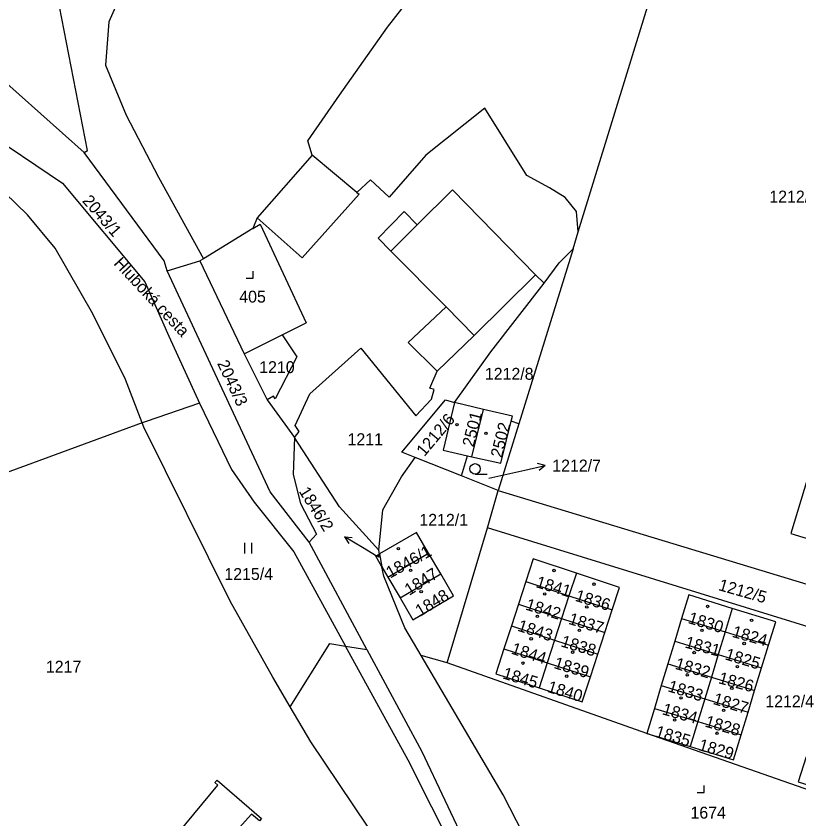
# Model space of a CAD drawing. Extents: x -679220 to -673243, y -1075091 to -1066557.
# Drawn here: x -676840.9 to -676729.1, y -1070923.7 to -1070809.1 of the extents above; entities that cross this region are included whole.
import ezdxf

# ---------------------------------------------------------------- set-up
doc = ezdxf.new("R2010")
doc.units = 0
for name, color, linetype in [('Hranice parcel', 7, 'Continuous'), ('Parcelní čísla', 7, 'Continuous'), ('Pop  PČ popisy', 7, 'Continuous'), ('Vnitřní kresba', 7, 'Continuous'), ('Značky budov', 7, 'Continuous'), ('Značky kultur', 7, 'Continuous')]:
    doc.layers.add(name, color=color, linetype=linetype)

msp = doc.modelspace()

# ---------------------------------------------------------------- linework, layer by layer
at = {"layer": 'Hranice parcel'}
for p, q in [((-676850.18, -1070811.62), (-676831.16, -1070828.55)), ((-676761.35, -1070842.3), (-676760.61, -1070839.9)), ((-676761.35, -1070842.3), (-676769.07, -1070867.29)), ((-676819.29, -1070845.47), (-676814.64, -1070844.06)), ((-676814.12, -1070843.75), (-676814.64, -1070844.06)), ((-676814.64, -1070844.06), (-676808.28, -1070857.3)), ((-676808.28, -1070857.3), (-676805.03, -1070863.88)), ((-676805.03, -1070863.88), (-676801.1, -1070869.26)), ((-676774.15, -1070865.26), (-676778.29, -1070864.28)), ((-676775.78, -1070872.01), (-676774.15, -1070865.26)), ((-676769.07, -1070867.29), (-676772.02, -1070876.85)), ((-676769.07, -1070867.29), (-676770.18, -1070866.92)), ((-676777.29, -1070874.76), (-676783.89, -1070872.14)), ((-676777.29, -1070874.76), (-676776.4, -1070871.87)), ((-676776.4, -1070871.87), (-676775.78, -1070872.01)), ((-676772.02, -1070876.85), (-676777.29, -1070874.76)), ((-676773.55, -1070882.16), (-676772.02, -1070876.85)), ((-676772.02, -1070876.85), (-676699.58, -1070898.82)), ((-676779.3, -1070901.45), (-676773.55, -1070882.16)), ((-676696.97, -1070905.8), (-676773.55, -1070882.16)), ((-676790.8, -1070899.53), (-676799.03, -1070884.19)), ((-676788.98, -1070885.89), (-676789.09, -1070885.34)), ((-676788.98, -1070885.89), (-676788.63, -1070887.71)), ((-676787.77, -1070889.19), (-676781.97, -1070885.79)), ((-676780.23, -1070888.75), (-676781.97, -1070885.79)), ((-676788.63, -1070887.71), (-676787.77, -1070889.19)), ((-676787.77, -1070889.19), (-676786.03, -1070892.17)), ((-676786.03, -1070892.17), (-676780.23, -1070888.75)), ((-676760.88, -1070888.63), (-676761.93, -1070891.86)), ((-676768.09, -1070889.83), (-676769.15, -1070893.08)), ((-676768.09, -1070889.83), (-676761.93, -1070891.86)), ((-676761.93, -1070891.86), (-676762.99, -1070895.1)), ((-676761.93, -1070891.86), (-676755.78, -1070893.89)), ((-676769.15, -1070893.08), (-676770.16, -1070896.18)), ((-676769.15, -1070893.08), (-676762.99, -1070895.1)), ((-676756.83, -1070897.12), (-676755.78, -1070893.89)), ((-676738.62, -1070893.67), (-676739.64, -1070897.02)), ((-676762.99, -1070895.1), (-676763.99, -1070898.2)), ((-676762.99, -1070895.1), (-676756.83, -1070897.12)), ((-676745.85, -1070895.11), (-676746.83, -1070898.36)), ((-676745.85, -1070895.11), (-676739.64, -1070897.02)), ((-676770.16, -1070896.18), (-676771.21, -1070899.42)), ((-676770.16, -1070896.18), (-676763.99, -1070898.2)), ((-676757.83, -1070900.21), (-676756.83, -1070897.12)), ((-676739.64, -1070897.02), (-676740.63, -1070900.26)), ((-676739.64, -1070897.02), (-676733.45, -1070898.92)), ((-676763.99, -1070898.2), (-676765.05, -1070901.43)), ((-676763.99, -1070898.2), (-676757.83, -1070900.21)), ((-676746.83, -1070898.36), (-676747.81, -1070901.6)), ((-676746.83, -1070898.36), (-676740.63, -1070900.26)), ((-676793.82, -1070899.05), (-676790.8, -1070899.53)), ((-676771.21, -1070899.42), (-676765.05, -1070901.43)), ((-676734.44, -1070902.16), (-676733.45, -1070898.92)), ((-676779.3, -1070901.45), (-676783.03, -1070900.39)), ((-676758.87, -1070903.44), (-676757.83, -1070900.21)), ((-676740.63, -1070900.26), (-676741.61, -1070903.5)), ((-676740.63, -1070900.26), (-676734.44, -1070902.16)), ((-676765.05, -1070901.43), (-676766.21, -1070905)), ((-676765.05, -1070901.43), (-676758.87, -1070903.44)), ((-676747.81, -1070901.6), (-676748.75, -1070904.69)), ((-676747.81, -1070901.6), (-676741.61, -1070903.5)), ((-676735.43, -1070905.39), (-676734.44, -1070902.16)), ((-676741.61, -1070903.5), (-676742.56, -1070906.59)), ((-676741.61, -1070903.5), (-676735.43, -1070905.39)), ((-676748.75, -1070904.69), (-676749.74, -1070907.94)), ((-676748.75, -1070904.69), (-676742.56, -1070906.59)), ((-676736.37, -1070908.49), (-676735.43, -1070905.39)), ((-676742.56, -1070906.59), (-676743.55, -1070909.83)), ((-676742.56, -1070906.59), (-676736.37, -1070908.49)), ((-676749.74, -1070907.94), (-676743.55, -1070909.83)), ((-676737.36, -1070911.72), (-676736.37, -1070908.49)), ((-676743.55, -1070909.83), (-676744.63, -1070913.39)), ((-676743.55, -1070909.83), (-676737.36, -1070911.72))]:
    msp.add_line(p, q, dxfattribs=at)
for points in [[(-676734.09, -1070729.39), (-676764.56, -1070754.12), (-676779.02, -1070765.48), (-676780.93, -1070766.95), (-676802.84, -1070783.93), (-676807.58, -1070787.57), (-676808.32, -1070787.51), (-676809.11, -1070788.09), (-676821.6, -1070800.12), (-676825.36, -1070804.84), (-676827.62, -1070809.91), (-676828.1, -1070816.09), (-676825.15, -1070823.23), (-676820.55, -1070832.07), (-676814.12, -1070843.75)], [(-676798.59, -1070828.95), (-676799.22, -1070826.91), (-676794.71, -1070820.4), (-676787.84, -1070810.66), (-676782.89, -1070804.27), (-676771.75, -1070792.62), (-676763.59, -1070784.6), (-676760.67, -1070781.6), (-676757.85, -1070778.9), (-676751.9, -1070773.46), (-676738.69, -1070761.14), (-676736.91, -1070759.79)], [(-676760.61, -1070839.9), (-676739.25, -1070770.5), (-676736.91, -1070759.79)], [(-676831.16, -1070828.55), (-676830.66, -1070828.28), (-676835.31, -1070804.23), (-676835.34, -1070801.91)], [(-676760.61, -1070839.9), (-676760.86, -1070836.98), (-676762.5, -1070834.99), (-676764.73, -1070833.61), (-676767.96, -1070831.87), (-676773.95, -1070822.25), (-676782.38, -1070828.97), (-676787.6, -1070834.96), (-676790.26, -1070832.45), (-676792.2, -1070834.26), (-676798.59, -1070828.95)], [(-676845.83, -1070825.14), (-676834.24, -1070832.94), (-676822.47, -1070847.02), (-676819.06, -1070854.79), (-676814.69, -1070864.34)], [(-676819.29, -1070845.47), (-676819.7, -1070844.03), (-676831.16, -1070828.55)], [(-676822.86, -1070867.17), (-676825.24, -1070860.98), (-676829.9, -1070851.62), (-676835.29, -1070842.22), (-676839.22, -1070837.48), (-676844.14, -1070832.76), (-676850.26, -1070829.73), (-676854.56, -1070828.9), (-676867.18, -1070828.96), (-676881.19, -1070830.31), (-676893.95, -1070833.16), (-676902.82, -1070835.91), (-676908.31, -1070838.15), (-676916.87, -1070843.08)], [(-676798.59, -1070828.95), (-676806.44, -1070837.88), (-676807.04, -1070839.43), (-676814.12, -1070843.75)], [(-676765.49, -1070847.23), (-676763.35, -1070844.34), (-676761.35, -1070842.3)], [(-676799.03, -1070884.19), (-676804.58, -1070877.03), (-676819.29, -1070845.47)], [(-676801.1, -1070869.26), (-676800.43, -1070868.39), (-676801.03, -1070867.56), (-676798.93, -1070863.04), (-676791.65, -1070856.53), (-676783.8, -1070866.15), (-676781.54, -1070863.79), (-676781.17, -1070862.41), (-676781.81, -1070862.24), (-676780.76, -1070859.8), (-676775.45, -1070854.68), (-676766.7, -1070846.03), (-676765.49, -1070847.23)], [(-676778.29, -1070864.28), (-676773.11, -1070857.01), (-676765.49, -1070847.23)], [(-676808.28, -1070857.3), (-676802.86, -1070854.59), (-676800.77, -1070857.75), (-676803.88, -1070863.73), (-676804.12, -1070863.35), (-676805.03, -1070863.88)], [(-676783.89, -1070872.14), (-676785.8, -1070871.38), (-676779.54, -1070863.89), (-676778.29, -1070864.28)], [(-676778.29, -1070864.28), (-676779.91, -1070871.08), (-676776.4, -1070871.87)], [(-676814.69, -1070864.34), (-676822.28, -1070866.96), (-676822.86, -1070867.17)], [(-676814.69, -1070864.34), (-676810.13, -1070873.84), (-676806.85, -1070878.49), (-676801.21, -1070885.59), (-676793.82, -1070899.05)], [(-676770.18, -1070866.92), (-676770.01, -1070866.24), (-676774.15, -1070865.26)], [(-676822.86, -1070867.17), (-676869.87, -1070884.46), (-676886.71, -1070890.82), (-676892.44, -1070892.97)], [(-676801.72, -1070907.71), (-676804.2, -1070903.47), (-676810.32, -1070892.65), (-676822.62, -1070867.79), (-676822.86, -1070867.17)], [(-676775.78, -1070872.01), (-676771.65, -1070872.94), (-676770.18, -1070866.92)], [(-676801.1, -1070869.26), (-676801.29, -1070874.56), (-676800.25, -1070878.69), (-676797.99, -1070883.05), (-676799.03, -1070884.19)], [(-676789.09, -1070885.34), (-676794.7, -1070879.18), (-676801.1, -1070869.26)], [(-676789.09, -1070885.34), (-676788.51, -1070879.57), (-676785.84, -1070874.87), (-676783.89, -1070872.14)], [(-676727.9, -1070875.12), (-676730.26, -1070882.97), (-676706.09, -1070890.37)], [(-676781.97, -1070885.79), (-676783.71, -1070882.82), (-676788.98, -1070885.89)], [(-676788.63, -1070887.71), (-676789.51, -1070886.2), (-676788.98, -1070885.89)], [(-676760.88, -1070888.63), (-676767.03, -1070886.59), (-676768.09, -1070889.83)], [(-676783.03, -1070900.39), (-676785.36, -1070896.43), (-676788.38, -1070889.05), (-676788.63, -1070887.71)], [(-676786.03, -1070892.17), (-676784.21, -1070895.29), (-676778.41, -1070891.85), (-676780.23, -1070888.75)], [(-676755.78, -1070893.89), (-676754.73, -1070890.66), (-676760.88, -1070888.63)], [(-676738.62, -1070893.67), (-676744.82, -1070891.73), (-676745.85, -1070895.11)], [(-676733.45, -1070898.92), (-676732.41, -1070895.6), (-676738.62, -1070893.67)], [(-676801.72, -1070907.71), (-676796.07, -1070898.7), (-676793.82, -1070899.05)], [(-676752.03, -1070975.55), (-676752.29, -1070975.05), (-676759.61, -1070960.04), (-676764.95, -1070950.34), (-676771.37, -1070939.74), (-676778.11, -1070928.74), (-676784.88, -1070915.33), (-676793.82, -1070899.05)], [(-676790.8, -1070899.53), (-676782.96, -1070914.09), (-676776.35, -1070928.02), (-676769.47, -1070938.96), (-676763.01, -1070949.54), (-676757.67, -1070959.24), (-676749.85, -1070974.05), (-676746.19, -1070981.35), (-676745.88, -1070981.9)], [(-676771.21, -1070899.42), (-676772.38, -1070903), (-676766.21, -1070905)], [(-676760.79, -1070939.06), (-676765.58, -1070931.53), (-676771.32, -1070920.3), (-676783.03, -1070900.39)], [(-676704, -1070927.89), (-676750.82, -1070911.51), (-676779.3, -1070901.45)], [(-676766.21, -1070905), (-676760.03, -1070907), (-676758.87, -1070903.44)], [(-676769.77, -1070957.23), (-676774.29, -1070950.5), (-676780.8, -1070941.14), (-676790.67, -1070924.75), (-676798.78, -1070912.74), (-676801.72, -1070907.71)], [(-676749.74, -1070907.94), (-676750.82, -1070911.51), (-676744.63, -1070913.39)], [(-676744.63, -1070913.39), (-676738.43, -1070915.27), (-676737.36, -1070911.72)], [(-676728.08, -1070914.85), (-676729.21, -1070918.43), (-676723, -1070920.38)], [(-676805.81, -1070923.65), (-676806.13, -1070924.02), (-676807.27, -1070923.03), (-676809.85, -1070925.96), (-676792.74, -1070940.58), (-676800.91, -1070950.14), (-676818.02, -1070935.52), (-676822.59, -1070931.62), (-676812.04, -1070918.93), (-676812.49, -1070918.55), (-676812.17, -1070918.18), (-676805.81, -1070923.65)]]:
    msp.add_lwpolyline(points, dxfattribs=at)
at = {"layer": 'Pop  PČ popisy'}
for p, q in [((-676768.25, -1070873.93), (-676765.33, -1070873.26)), ((-676765.33, -1070873.26), (-676766.41, -1070872.99)), ((-676765.33, -1070873.26), (-676766.19, -1070873.97)), ((-676773.36, -1070875.08), (-676768.25, -1070873.93)), ((-676791.41, -1070884.99), (-676793.98, -1070883.44)), ((-676793.98, -1070883.44), (-676792.87, -1070883.53)), ((-676793.98, -1070883.44), (-676793.38, -1070884.39)), ((-676789.32, -1070886.25), (-676791.41, -1070884.99))]:
    msp.add_line(p, q, dxfattribs=at)
at = {"layer": 'Vnitřní kresba'}
for p, q in [((-676792.2, -1070834.26), (-676791.87, -1070834.54)), ((-676783.58, -1070838.89), (-676778.55, -1070833.92)), ((-676778.55, -1070833.92), (-676766.7, -1070846.03)), ((-676800.03, -1070843.59), (-676791.87, -1070834.54)), ((-676806.44, -1070837.88), (-676800.03, -1070843.59)), ((-676785.44, -1070837), (-676789.17, -1070840.81)), ((-676785.44, -1070837), (-676783.58, -1070838.89)), ((-676807.04, -1070839.43), (-676806.01, -1070838.8)), ((-676806.01, -1070838.8), (-676799.46, -1070852.89)), ((-676787.36, -1070842.64), (-676783.58, -1070838.89)), ((-676787.36, -1070842.64), (-676789.17, -1070840.81)), ((-676779.48, -1070850.61), (-676787.36, -1070842.64)), ((-676779.48, -1070850.61), (-676784.89, -1070855.69)), ((-676775.45, -1070854.68), (-676779.48, -1070850.61)), ((-676802.86, -1070854.59), (-676799.46, -1070852.89)), ((-676780.76, -1070859.8), (-676784.89, -1070855.69))]:
    msp.add_line(p, q, dxfattribs=at)
at = {"layer": 'Značky budov'}
for centre, radius in [((-676777.91, -1070867.44), 0.175), ((-676773.79, -1070868.68), 0.175), ((-676786.29, -1070885.14), 0.175), ((-676789.09, -1070886.22), 0.117), ((-676784.54, -1070888.23), 0.175), ((-676764.06, -1070888.26), 0.175), ((-676758.35, -1070890.21), 0.175), ((-676783.03, -1070891.27), 0.175), ((-676765.4, -1070891.61), 0.175), ((-676759.39, -1070893.46), 0.175), ((-676742.15, -1070893.39), 0.175), ((-676766.44, -1070894.79), 0.175), ((-676735.87, -1070895.38), 0.175), ((-676760.45, -1070896.81), 0.175), ((-676742.95, -1070896.79), 0.175), ((-676767.33, -1070898.01), 0.175), ((-676736.93, -1070898.68), 0.175), ((-676761.41, -1070899.92), 0.175), ((-676744.06, -1070899.97), 0.175), ((-676768.51, -1070901.48), 0.175), ((-676737.89, -1070902), 0.175), ((-676762.26, -1070903.34), 0.175), ((-676745.05, -1070903.16), 0.175), ((-676738.69, -1070905.09), 0.175), ((-676745.94, -1070906.45), 0.175), ((-676739.86, -1070908.22), 0.175), ((-676746.85, -1070909.61), 0.175), ((-676740.8, -1070911.49), 0.175)]:
    msp.add_circle(centre, radius, dxfattribs=at)
at = {"layer": 'Značky kultur'}
for p, q in [((-676807.02, -1070846.53), (-676807.02, -1070845.53)), ((-676808.02, -1070846.53), (-676807.02, -1070846.53)), ((-676775.34, -1070874.49), (-676773.59, -1070874.49)), ((-676808.2, -1070885.81), (-676808.2, -1070884.31)), ((-676807.2, -1070885.81), (-676807.2, -1070884.31)), ((-676742.62, -1070919.98), (-676742.62, -1070918.98)), ((-676743.62, -1070919.98), (-676742.62, -1070919.98))]:
    msp.add_line(p, q, dxfattribs=at)
msp.add_circle((-676775.34, -1070873.74), 0.75, dxfattribs=at)

# ---------------------------------------------------------------- texts
at = {"layer": 'Parcelní čísla'}
for s, p in [('1212/2', (-676733.33, -1070835.71)), ('405', (-676809, -1070850)), ('1210', (-676806.15, -1070860.07)), ('1212/8', (-676773.94, -1070861.02)), ('1211', (-676793.54, -1070870.36)), ('1212/7', (-676764.32, -1070874.12)), ('1212/1', (-676783.29, -1070881.87)), ('1215/4', (-676811.13, -1070889.61)), ('1217', (-676836.6, -1070902.84)), ('1212/4', (-676733.91, -1070907.78)), ('1674', (-676744.59, -1070923.68))]:
    msp.add_text(s, height=1.7, dxfattribs=at).set_placement(p)
for s, rotation, p in [('2043/1', 311, (-676831.5, -1070835.52)), ('2043/3', 295, (-676812.19, -1070858.67)), ('1212/6', 50, (-676782.57, -1070872.07)), ('2501', 76, (-676775.55, -1070870.72)), ('2502', 76, (-676771.51, -1070872.26)), ('1846/2', 302, (-676800.55, -1070876.95)), ('1846/1', 29, (-676787.46, -1070889.42)), ('1847', 32, (-676784.74, -1070891.89)), ('1841', 343, (-676766.78, -1070890.61)), ('1212/5', 344, (-676740.7, -1070891.04)), ('1848', 31, (-676783.22, -1070894.89)), ('1836', 343, (-676761.17, -1070892.56)), ('1842', 343, (-676768.24, -1070893.82)), ('1837', 343, (-676762.11, -1070895.86)), ('1830', 343, (-676745.04, -1070895.74)), ('1843', 342, (-676769.39, -1070896.83)), ('1824', 344, (-676738.76, -1070897.71)), ('1844', 342, (-676770.3, -1070900.1)), ('1838', 343, (-676763.21, -1070899.07)), ('1831', 345, (-676745.49, -1070899.24)), ('1825', 343, (-676739.77, -1070900.93)), ('1839', 343, (-676764.21, -1070902.17)), ('1832', 344, (-676746.9, -1070902.28)), ('1845', 343, (-676771.52, -1070903.64)), ('1826', 345, (-676740.7, -1070904.34)), ('1840', 343, (-676765.14, -1070905.57)), ('1833', 343, (-676747.93, -1070905.49)), ('1827', 343, (-676741.48, -1070907.29)), ('1834', 344, (-676748.73, -1070908.77)), ('1828', 344, (-676742.63, -1070910.53)), ('1835', 343, (-676749.74, -1070911.96)), ('1829', 344, (-676743.55, -1070913.88))]:
    msp.add_text(s, height=1.7, rotation=rotation, dxfattribs=at).set_placement(p)
at = {"layer": 'Pop  PČ popisy'}
msp.add_text('Hluboká cesta', height=1.7, rotation=313, dxfattribs=at).set_placement((-676827.02, -1070844.49))

doc.saveas('drawing.dxf')
